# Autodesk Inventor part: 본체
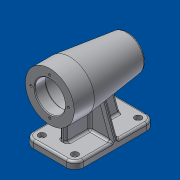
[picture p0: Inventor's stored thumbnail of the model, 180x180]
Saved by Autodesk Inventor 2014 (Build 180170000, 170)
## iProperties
Created: 2018-09
Part Number: 본체
Material: 알루미늄 6061
Document SubType Name: Modeling
Designer: 702-20
Density: 2.71 g/cm^3
Appearance: 알루미늄 - 평지
Mass: 736.704 g
Surface Area: 677.019 cm^2
Volume: 271.846 cm^3
Author: 702-20
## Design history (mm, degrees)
sketch "스케치5"
  geometry: C1 r 34 at (0, 0); 1 further point
  constraints: 1 centre point, 1 coincident
  dimensions: "d16" = 68 diameter of C1
extrude "돌출1" new body sketch "스케치5" distance "d17" = 28; taper "d18" = 0 deg
sketch "스케치6"
  geometry: C1 r 34 at (0, 0) reference
extrude "돌출2" join sketch "스케치6" distance "d19" = 92; taper "d20" = -7 deg
sketch "스케치7"
  geometry: L1 (0, 34)-(28, 34) reference; L2 (0, 34)-(0, -34) reference; L3 (0, -34)-(28, -34) reference; L4 (0, 34)-(117.083, 34); L5 (0, -34)-(117.083, -34); L6 (0, 0)-(112, 0); A1 r 80 centre (32, 0) between (104.415, -34) and (104.415, 34)
  constraints: 6 end point, 4 parallel, 3 point on circle, 2 point on line, 1 centre point
  dimensions: "d21" = 112 distance of L6.end L6.start; "d22" = 80 radius of A1
node "작업 평면2"
sketch "스케치8"
  geometry: L1 (-34, 0)-(-34, 28) reference; L2 (34, 0)-(34, 28) reference; L3 (-34, 0)-(34, 0) reference; L4 (-34, 0)-(-34, 112.065); L5 (34, 0)-(34, 112.065); A1 r 80 centre (-0.332, 24.439) between (45.834, 89.774) and (-45.954, 90.155); 3 further points
  constraints: 4 end point, 3 point on circle, 2 parallel, 1 centre point, 1 coincident, 1 perpendicular, 1 other
  dimensions: "d23" = 80 radius of A1
feature "스윕 곡면2" sketch "스케치8" dims "d24" = 0
feature "분할2"
sketch "스케치9"
  geometry: L1 (0, 0)-(0, 118.713); L2 (0, 106)-(7.5, 106); L3 (10.5, 103)-(10.5, 103); L4 (10.5, 103)-(15.7, 103); L5 (16, 102.7)-(16, 99); L6 (16, 99)-(17.2, 99); L7 (17.5, 98.7)-(17.5, 81); L8 (17.5, 81)-(20.7, 81); L9 (21, 80.7)-(21, 69); L10 (21, 69)-(21, 69); L11 (24, 66)-(24, 18); L12 (21, 15)-(21, 15); L13 (21, 15)-(21, 0); L14 (21, 0)-(0, 0); A1 r 3 centre (7.5, 103) between (10.5, 103) and (7.5, 106); A2 r 3 centre (21, 66) between (24, 66) and (21, 69); A3 r 3 centre (21, 18) between (21, 15) and (24, 18); A4 r 0.3 centre (15.7, 102.7) between (16, 102.7) and (15.7, 103); A5 r 0.3 centre (17.2, 98.7) between (17.5, 98.7) and (17.2, 99); A6 r 0.3 centre (20.7, 80.7) between (21, 80.7) and (20.7, 81); 3 further points
  constraints: 28 end point, 12 point on circle, 12 tangent, 9 parallel, 7 point on line, 6 centre point, 4 equal radius, 4 perpendicular, 1 vertical
  dimensions: "d25" = 15 distance between parallel lines of L14 L12; "d26" = 54 distance between parallel lines of L10 L12; "d27" = 12 distance between parallel lines of L8 L10; "d28" = 18 distance from line of L5.end L8; "d29" = 4 vertical distance of point (16, 103) point (17.5, 99); "d30" = 3 distance between parallel lines of L2 L4; "d31" = 42 diameter of L13 L1; "d32" = 48 diameter of L11 L1; "d33" = 42 diameter of L9 L1; "d34" = 35 diameter of L7 L1; "d35" = 32 diameter of L5 L1; "d36" = 21 diameter of point (10.5, 106) L1; "d37" = 3 radius of A1; "d38" = 0.3 radius of A4
revolve "회전2" sketch "스케치9" stored, may be unused: angle "d39" = 90 deg
node "작업 평면3"
sketch "스케치10"
  geometry: L1 (-23, 112)-(23, 112); L2 (35, 100)-(35, 12); L3 (23, 0)-(-23, 0); L4 (-35, 12)-(-35, 100); A1 r 12 centre (-23, 100) between (-23, 112) and (-35, 100); A2 r 12 centre (23, 100) between (35, 100) and (23, 112); A3 r 12 centre (23, 12) between (23, 0) and (35, 12); A4 r 12 centre (-23, 12) between (-35, 12) and (-23, 0); 5 further points
  constraints: 8 end point, 8 point on circle, 8 tangent, 6 point on line, 4 centre point, 3 equal radius, 2 parallel, 1 coincident, 1 horizontal, 1 midpoint, 1 perpendicular
  dimensions: "d41" = 70 distance of point (35, 0) point (-35, 0); "d42" = 112 distance of point (35, 112) point (35, 0); "d43" = 12 radius of A1
extrude "돌출3" join sketch "스케치10" distance "d44" = 10; taper "d45" = 0 deg
sketch "스케치11"
  geometry: L1 (18, -31.243)-(18, -64); L2 (83.432, -24.56)-(94, -64); L3 (108.27, -24.144)-(28, -34) reference; L4 (28, -34)-(0, -34) reference; L5 (0, -34)-(0, -21) reference; L6 (0, -21)-(15, -21) reference; L7 (18, -24)-(66, -24) reference; L8 (69, -21)-(80.7, -21) reference; L9 (81, -20.7)-(81, -17.5) reference; L10 (81, -17.5)-(98.7, -17.5) reference; L11 (99, -17.2)-(99, -16) reference; L12 (99, -16)-(102.7, -16) reference; L13 (103, -15.7)-(103, -10.5) reference; L14 (106, -7.5)-(106, 7.5) reference; L15 (103, 10.5)-(103, 15.7) reference; L16 (102.7, 16)-(99, 16) reference; L17 (99, 16)-(99, 17.2) reference; L18 (98.7, 17.5)-(81, 17.5) reference; L19 (81, 17.5)-(81, 20.7) reference; L20 (80.7, 21)-(69, 21) reference; L21 (66, 24)-(18, 24) reference; L22 (15, 21)-(0, 21) reference; L23 (0, 21)-(0, 34) reference; L24 (0, 34)-(28, 34) reference; L25 (28, 34)-(108.27, 24.144) reference; L26 (0, -74)-(0, -64) reference; L27 (0, -64)-(112, -64) reference; L28 (112, -64)-(112, -74) reference; L29 (112, -74)-(0, -74) reference; L30 (18, -31.243)-(34.345, -31.243); L31 (34.345, -31.243)-(83.432, -24.56); A1 r 3 centre (18, -21) between (15, -21) and (18, -24) reference; A2 r 3 centre (66, -21) between (66, -24) and (69, -21) reference; A3 r 0.3 centre (80.7, -20.7) between (80.7, -21) and (81, -20.7) reference; A4 r 0.3 centre (98.7, -17.2) between (98.7, -17.5) and (99, -17.2) reference; A5 r 0.3 centre (102.7, -15.7) between (102.7, -16) and (103, -15.7) reference; A6 r 3 centre (103, -7.5) between (103, -10.5) and (106, -7.5) reference; A7 r 3 centre (103, 7.5) between (106, 7.5) and (103, 10.5) reference; A8 r 0.3 centre (102.7, 15.7) between (103, 15.7) and (102.7, 16) reference; A9 r 0.3 centre (98.7, 17.2) between (99, 17.2) and (98.7, 17.5) reference; A10 r 0.3 centre (80.7, 20.7) between (81, 20.7) and (80.7, 21) reference; A11 r 3 centre (66, 21) between (69, 21) and (66, 24) reference; A12 r 3 centre (18, 21) between (18, 24) and (15, 21) reference; 3 further points
  constraints: 8 end point, 6 point on line, 1 parallel, 1 vertical, 1 vertical alignment
  dimensions: "d46" = 18 distance from line of L2.end L28; "d47" = 18 distance between parallel lines of L1 L26; "d48" = 105 deg angle of L2 L27
extrude "돌출4" join sketch "스케치11" stored distance "d49" = 8; taper "d50" = 0 deg
node "작업 평면4"
sketch "스케치12"
  geometry: L1 (35, -64)-(35, -74) reference; L2 (35, -74)-(-35, -74) reference; L3 (-35, -74)-(-35, -64) reference; L4 (-35, -64)-(-4, -64) reference; L5 (-4, -64)-(-4, -30.562) reference; L6 (-4, -30.562)-(0, -30.562) reference; L7 (0, -30.562)-(4, -30.562) reference; L8 (4, -30.562)-(4, -64) reference; L9 (4, -64)-(35, -64) reference; L10 (-35, -64)-(-20.089, -23.032); C1 r 24 at (0, 0) reference; A1 r 30.562 centre (0, 0) between (0, -30.562) and (-20.089, -23.032) reference; 1 further point
  constraints: 2 end point, 1 point on circle
  dimensions: "d53" = 20 deg angle of L10 L3
feature "리브1" sketch "스케치12" dims "d54" = 1, "d55" = 8, "d56" = 0, "d57" = 0, "d58" = 1, "d59" = 1
fillet "모깎기1" dims "d60" = 3
fillet "모깎기2" dims "d61" = 3
fillet "모깎기3" dims "d62" = 3
fillet "모깎기4" dims "d63" = 3
fillet "모깎기5" dims "d64" = 3
fillet "모깎기6" dims "d65" = 3
hole "구멍1" diameter "d68" = 5.5; stored, may be unused: countersink angle "d72" = 90 deg, drill point angle "d74" = 118 deg; dims "d66" = 10, "d67" = 10, "d69" = 6, "d70" = 9.5, "d71" = 5.4, "d73" = 8
node "작업 평면5"
node "작업 평면6"
sketch "스케치13"
  geometry: C1 r 21 at (0, 0) reference; 1 further point
  dimensions: "d75" = 26 distance of C1.centre point (0, 26)
hole "구멍2" sketch "스케치13" at (0, 26) diameter "d76" = 3.242; stored, may be unused: countersink angle "d80" = 90 deg, drill point angle "d82" = 118 deg; dims "d77" = 8, "d78" = 9.5, "d79" = 5.4, "d81" = 11
chamfer "모따기1" distance "d86" = 1; stored, may be unused: second distance "d87" = 2, angle "d88" = 45 deg
sketch "스케치14"
  geometry: L1 (0, 88)-(0, 0) reference; L2 (7, 39.391)-(7, 0) reference; L3 (3, 110.486)-(3, -60.871); L4 (0, 44)-(17.321, 44); 2 further points
  constraints: 4 end point, 1 midpoint, 1 parallel, 1 perpendicular, 1 other
  dimensions: "d89" = 3 distance between parallel lines of L3 L1
feature "엠보싱1" sketch "스케치14" dims "d90" = 0.5, "d91" = 0
fillet "모깎기7" dims "d92" = 3
fillet "모깎기8" dims "d93" = 3
node "솔리드2"
mirror "대칭1"
mirror "대칭2"
mirror "대칭3"
pattern_circular "원형 패턴1" dims angle "d84" = 360 deg
node "곡면3"
node "절단 모서리 투영1"
node "절단 모서리 투영2"
other parameters: "d40" = -74, "d51" = 56
